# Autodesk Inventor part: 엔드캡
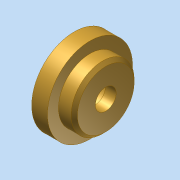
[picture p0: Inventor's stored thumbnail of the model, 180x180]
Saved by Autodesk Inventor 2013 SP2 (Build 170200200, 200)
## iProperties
Created: 2026-01
Part Number: 엔드캡
Material: Generic
Document SubType Name: Modeling
Designer: a
Density: 1 g/cm^3
Author: a
변환 표준: STEP AP214IS
전처리기: Build: 200, Release: 2013 SP2 Update 6 - Date: Thu 07/17/2014
전송 단위: 밀리미터
불확실성: 0.01
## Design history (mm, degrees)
node "엔드캡1"
node "솔리드1"
node "기준1"
